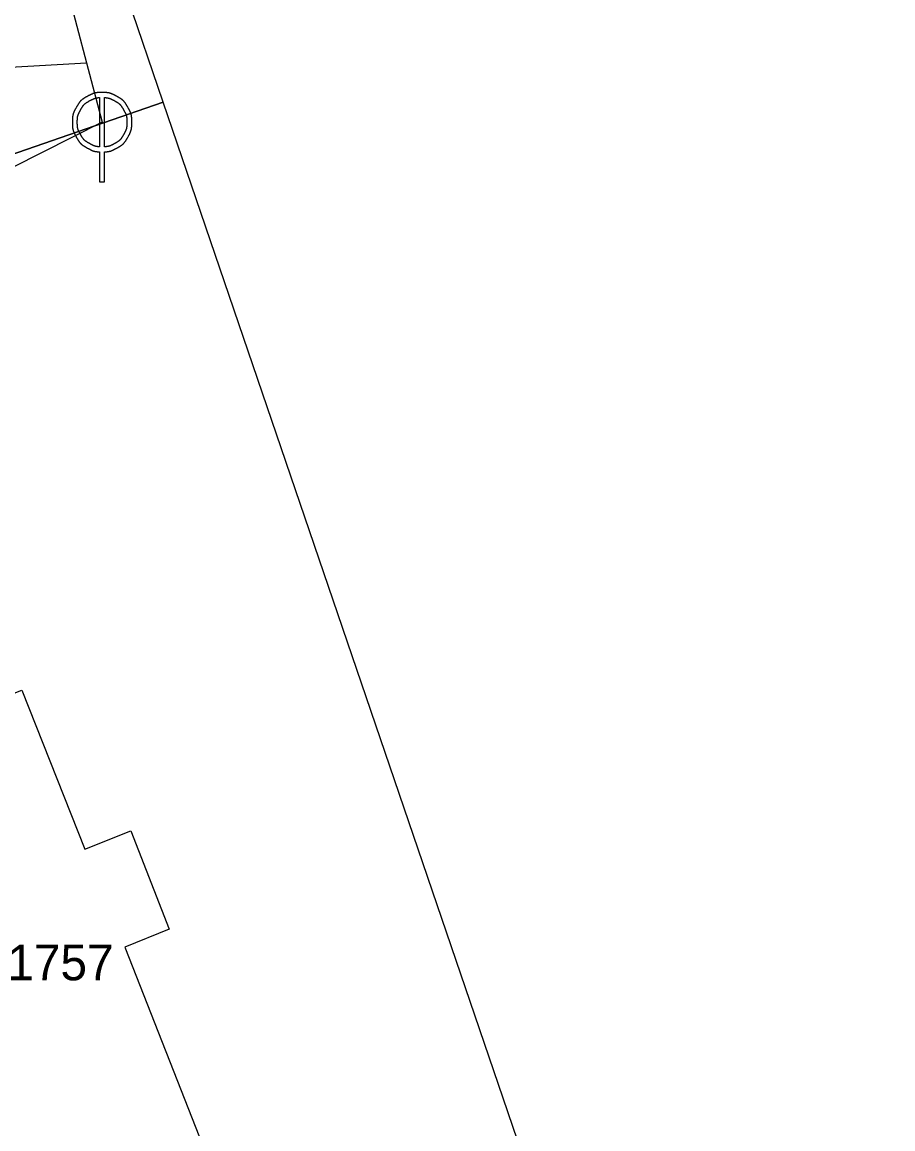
# Model space of a CAD drawing. Extents: x -562248 to -562040, y -1079385 to -1079027.
# Drawn here: x -562087.3 to -562050.73, y -1079196.27 to -1079149.79 of the extents above; entities that cross this region are included whole.
import ezdxf

# ---------------------------------------------------------------- set-up
doc = ezdxf.new("R2010")
doc.units = 0
for name, color, linetype in [('Default', 7, 'Continuous'), ('Kanalizační přípojka', 7, 'Continuous'), ('Kanalizační stoka', 7, 'Continuous'), ('Kanalizační šachta', 7, 'Continuous'), ('Parcela-polygon', 7, 'Continuous'), ('Parcela-text', 7, 'Continuous')]:
    doc.layers.add(name, color=color, linetype=linetype)

msp = doc.modelspace()

# ---------------------------------------------------------------- linework, layer by layer
at = {"layer": 'Default'}
for points in [[(-562083.94, -1079152.74), (-562084.152, -1079152.74), (-562084.357, -1079152.794), (-562084.555, -1079152.901)], [(-562083.326, -1079152.901), (-562083.525, -1079152.794), (-562083.73, -1079152.74), (-562083.94, -1079152.74)], [(-562085.022, -1079153.363), (-562085.134, -1079153.563), (-562085.19, -1079153.772), (-562085.19, -1079153.99)], [(-562084.555, -1079152.901), (-562084.754, -1079153.009), (-562084.909, -1079153.162), (-562085.022, -1079153.363)], [(-562084.843, -1079153.469), (-562084.751, -1079153.302), (-562084.621, -1079153.174), (-562084.455, -1079153.084)], [(-562084.455, -1079153.084), (-562084.312, -1079153.008), (-562084.174, -1079152.964), (-562084.043, -1079152.952)], [(-562083.837, -1079152.952), (-562083.706, -1079152.964), (-562083.569, -1079153.008), (-562083.427, -1079153.084)], [(-562083.427, -1079153.084), (-562083.261, -1079153.174), (-562083.131, -1079153.302), (-562083.038, -1079153.469)], [(-562082.858, -1079153.363), (-562082.971, -1079153.162), (-562083.127, -1079153.009), (-562083.326, -1079152.901)], [(-562082.69, -1079153.99), (-562082.69, -1079153.772), (-562082.746, -1079153.563), (-562082.858, -1079153.363)], [(-562084.982, -1079153.99), (-562084.982, -1079153.809), (-562084.936, -1079153.636), (-562084.843, -1079153.469)], [(-562083.038, -1079153.469), (-562082.944, -1079153.636), (-562082.898, -1079153.809), (-562082.898, -1079153.99)], [(-562085.19, -1079153.99), (-562085.19, -1079154.206), (-562085.135, -1079154.414), (-562085.025, -1079154.613)], [(-562084.846, -1079154.508), (-562084.937, -1079154.343), (-562084.982, -1079154.171), (-562084.982, -1079153.99)], [(-562082.898, -1079153.99), (-562082.898, -1079154.171), (-562082.943, -1079154.343), (-562083.034, -1079154.508)], [(-562082.855, -1079154.613), (-562082.745, -1079154.414), (-562082.69, -1079154.206), (-562082.69, -1079153.99)], [(-562085.025, -1079154.613), (-562084.915, -1079154.811), (-562084.761, -1079154.965), (-562084.563, -1079155.074)], [(-562084.46, -1079154.891), (-562084.626, -1079154.8), (-562084.755, -1079154.672), (-562084.846, -1079154.508)], [(-562083.034, -1079154.508), (-562083.125, -1079154.672), (-562083.253, -1079154.8), (-562083.418, -1079154.891)], [(-562083.317, -1079155.074), (-562083.119, -1079154.965), (-562082.965, -1079154.811), (-562082.855, -1079154.613)], [(-562084.563, -1079155.074), (-562084.388, -1079155.172), (-562084.215, -1079155.226), (-562084.043, -1079155.238)], [(-562084.043, -1079155.025), (-562084.179, -1079155.015), (-562084.318, -1079154.971), (-562084.46, -1079154.891)], [(-562083.418, -1079154.891), (-562083.561, -1079154.971), (-562083.701, -1079155.015), (-562083.837, -1079155.025)], [(-562083.837, -1079155.238), (-562083.665, -1079155.226), (-562083.492, -1079155.172), (-562083.317, -1079155.074)]]:
    msp.add_open_spline(points, degree=2, dxfattribs=at)
at = {"layer": 'Kanalizační přípojka'}
msp.add_lwpolyline([(-562088.3, -1079151.71), (-562084.597, -1079151.5)], dxfattribs=at)
at = {"layer": 'Kanalizační stoka'}
for points in [[(-562093.623, -1079117.284), (-562092.416, -1079121.861), (-562090.3, -1079129.88), (-562088.21, -1079137.78), (-562086.63, -1079143.78), (-562084.597, -1079151.5), (-562083.94, -1079153.99)], [(-562083.94, -1079153.99), (-562095.303, -1079159.733), (-562108.95, -1079166.63)]]:
    msp.add_lwpolyline(points, dxfattribs=at)
at = {"layer": 'Kanalizační šachta'}
for points in [[(-562084.043, -1079152.952), (-562084.043, -1079155.025)], [(-562083.837, -1079155.025), (-562083.837, -1079152.952)], [(-562084.043, -1079156.49), (-562083.837, -1079156.49), (-562083.837, -1079155.238)], [(-562084.043, -1079155.238), (-562084.043, -1079156.49)]]:
    msp.add_lwpolyline(points, dxfattribs=at)
at = {"layer": 'Parcela-polygon'}
for p, q in [((-562081.378, -1079153.144), (-562097.98, -1079104.526)), ((-562050.734, -1079242.89), (-562081.378, -1079153.144))]:
    msp.add_line(p, q, dxfattribs=at)
for points in [[(-562097.98, -1079104.526), (-562122.92, -1079108.96), (-562122.79, -1079112.89), (-562122.55, -1079115.89), (-562121.94, -1079119.29), (-562120.22, -1079128.2), (-562118.94, -1079132.53), (-562115.47, -1079143.79), (-562113.13, -1079150.92), (-562110.57, -1079158.43), (-562109.03, -1079162.72), (-562081.378, -1079153.144)], [(-562081.378, -1079153.144), (-562109.03, -1079162.72), (-562108.26, -1079165.24), (-562101.64, -1079183.14), (-562103.67, -1079183.92), (-562098.96, -1079196.12), (-562094.66, -1079207.06), (-562088.81, -1079221.44), (-562081.96, -1079237.32), (-562074.7, -1079253.09), (-562050.734, -1079242.89)], [(-562087.31, -1079177.84), (-562084.66, -1079184.52), (-562082.74, -1079183.76), (-562081.12, -1079187.88), (-562082.98, -1079188.64), (-562079.54, -1079197.41), (-562076.16, -1079205.92), (-562074.23, -1079205.15), (-562072.6, -1079209.24), (-562074.46, -1079209.98), (-562072.57, -1079214.96), (-562069.67, -1079222.27), (-562067.79, -1079221.53), (-562066.16, -1079225.6), (-562068.03, -1079226.3), (-562065.74, -1079232.15), (-562074.99, -1079235.83), (-562081.83, -1079218.64), (-562086.76, -1079206.22), (-562087.15, -1079205.27), (-562088.06, -1079205.65)]]:
    msp.add_lwpolyline(points, dxfattribs=at)
msp.add_lwpolyline([(-562096.6, -1079181.53), (-562087.31, -1079177.84), (-562084.66, -1079184.52), (-562082.74, -1079183.76), (-562081.12, -1079187.88), (-562082.98, -1079188.64), (-562079.54, -1079197.41), (-562089.73, -1079201.46), (-562091.4, -1079197.27), (-562090.48, -1079196.9)], close=True, dxfattribs=at)

# ---------------------------------------------------------------- texts
at = {"layer": 'Parcela-text'}
msp.add_text('1757', height=1.5, dxfattribs=at).set_placement((-562087.92, -1079190.03))

doc.saveas('drawing.dxf')
